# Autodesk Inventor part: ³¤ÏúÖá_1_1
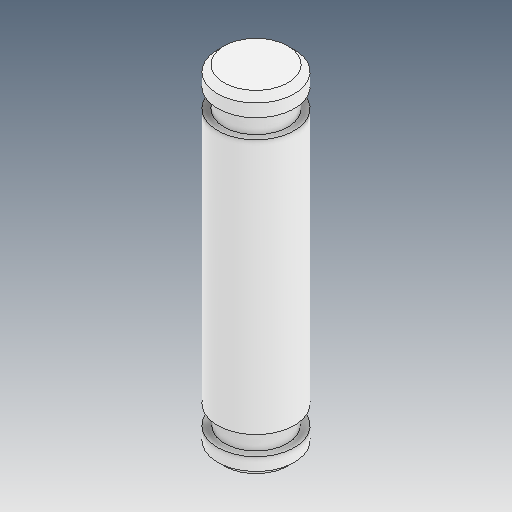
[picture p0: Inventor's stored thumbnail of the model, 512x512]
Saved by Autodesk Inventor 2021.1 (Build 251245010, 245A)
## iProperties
Created: 2021-05
Part Number: ³¤ÏúÖá_1_1
Material: Ogólny
Document SubType Name: Modeling
Designer: user
Density: 1 g/cm^3
Appearance: Domyślna
Author: user
Revision Number: ÈÎºÎ
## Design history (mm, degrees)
feature "ÊäÈë1"
node "Bryła1"
